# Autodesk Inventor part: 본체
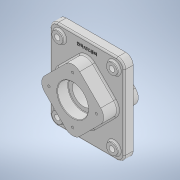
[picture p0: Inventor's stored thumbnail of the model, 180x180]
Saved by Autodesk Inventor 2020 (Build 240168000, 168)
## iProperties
Created: 2021-07
Part Number: 본체
Material: 일반
Document SubType Name: Modeling
Designer: Owner
Density: 1 g/cm^3
Appearance: 기본값
Author: Owner
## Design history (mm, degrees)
sketch "스케치1"
  geometry: L1 (75, 90)-(-75, 90); L2 (-75, 90)-(-75, -90); L3 (-75, -90)-(75, -90); L4 (75, -90)-(75, 90); L5 (75, 90)-(-75, -90); L6 (-75, 90)-(75, -90); 1 further point
  constraints: 12 end point, 2 midpoint, 2 parallel, 1 horizontal, 1 perpendicular
  dimensions: "d0" = 150 distance of L1.start L1.end; "d1" = 180 distance between parallel lines of L3 L1
extrude "돌출1" new body sketch "스케치1" stored distance "d2" = 18; taper "d3" = 0 deg
sketch "스케치2"
  geometry: L1 (-56.569, 14.142)-(-14.142, 56.569); L2 (14.142, 56.569)-(56.569, 14.142); L3 (56.569, -14.142)-(14.142, -56.569); L4 (-14.142, -56.569)-(-56.569, -14.142); L5 (-70.711, 0)-(70.711, 0); L6 (0, 70.711)-(0, -70.711); A1 r 20 centre (0, 42.426) between (14.142, 56.569) and (-14.142, 56.569); A2 r 20 centre (42.426, 0) between (56.569, -14.142) and (56.569, 14.142); A3 r 20 centre (0, -42.426) between (-14.142, -56.569) and (14.142, -56.569); A4 r 20 centre (-42.426, 0) between (-56.569, 14.142) and (-56.569, -14.142); 1 further point
  constraints: 12 end point, 8 point on circle, 8 point on line, 8 tangent, 4 centre point, 3 equal radius, 2 midpoint, 2 parallel, 1 perpendicular, 1 vertical
  dimensions: "d4" = 100 distance of L6.start L5.end; "d5" = 45 deg angle of L6 L2; "d6" = 20 radius of A1
extrude "돌출2" join sketch "스케치2" distance "d7" = 29; taper "d8" = 0 deg
extrude "돌출3" join sketch "스케치2" distance "d9" = 41; taper "d10" = 0 deg
sketch "스케치3"
  geometry: L1 (0, 38)-(0, -32); L2 (-14.142, -32)-(14.142, -32) reference; L3 (56.569, 38)-(14.142, 38) reference; L4 (31, 38)-(31, 16); L5 (31, 16)-(22.5, 16); L6 (22.5, 16)-(22.5, -10); L7 (31, -10)-(31, -32); L8 (14.142, -32)-(56.569, -32) reference; L9 (31, -10)-(22.5, -10); L10 (14.142, 38)-(-14.142, 38) reference; 1 further point
  constraints: 12 end point, 4 point on line, 2 vertical, 1 midpoint, 1 perpendicular
  dimensions: "d11" = 62 diameter of L4 L1; "d12" = 45 diameter of L6 L1; "d13" = 22 distance between parallel lines of L5 L3; "d14" = 22 distance between parallel lines of L8 L9
revolve "회전1" sketch "스케치3" stored, may be unused: angle "d15" = 90 deg
fillet "모깎기1" dims "d16" = 15
sketch "스케치4"
  geometry: 2 further points
  constraints: 1 vertical alignment
  dimensions: "d17" = 48 distance of point (0, 0) point (0, 48)
hole "구멍1" sketch "스케치4" at (0, 48) diameter "d18" = 4.917; stored, may be unused: countersink angle "d22" = 90 deg, drill point angle "d24" = 118 deg; dims "d19" = 10, "d20" = 4, "d21" = 2, "d23" = 13
sketch "스케치5"
  geometry: 2 further points
  constraints: 1 vertical alignment
  dimensions: "d28" = 48 distance of point (0, 0) point (0, 48)
hole "구멍2" sketch "스케치5" at (0, 48) diameter "d29" = 4.917; stored, may be unused: countersink angle "d33" = 90 deg, drill point angle "d35" = 118 deg; dims "d30" = 10, "d31" = 4, "d32" = 2, "d34" = 13
sketch "스케치6"
  geometry: L1 (60, 90)-(-60, 90) reference; L2 (75, -75)-(75, 75) reference; L3 (-75, 75)-(-75, -75) reference; C1 r 11 at (55, 70); C2 r 11 at (-55, 70); 1 further point
  constraints: 2 centre point
  dimensions: "d39" = 22 diameter of C1; "d40" = 20 distance from line of L1 C1.centre; "d41" = 20 distance from line of L2 C1.centre; "d42" = 22 diameter of C2; "d43" = 110 distance of C1.centre C2.centre; "d44" = 20 distance from line of L3 C2.centre
extrude "돌출4" join sketch "스케치6" distance "d45" = 5; taper "d46" = 0 deg
sketch "스케치7"
  geometry: C1 r 11 at (0, 0) reference; 2 further points
  constraints: 1 coincident
hole "구멍3" sketch "스케치7" at (0, 0) diameter "d47" = 11; stored, may be unused: countersink angle "d51" = 90 deg, drill point angle "d53" = 0 deg; dims "d48" = 10, "d49" = 4, "d50" = 2, "d52" = 13
fillet "모깎기2" dims "d54" = 3
fillet "모깎기3" dims "d55" = 3
fillet "모깎기4" dims "d56" = 3
fillet "모깎기5" dims "d57" = 1
chamfer "모따기1" distance "d58" = 1; stored, may be unused: second distance "d59" = 2, angle "d60" = 45 deg
chamfer "모따기2" distance "d61" = 1; stored, may be unused: second distance "d62" = 2, angle "d63" = 45 deg
sketch "스케치8"
  geometry: L1 (60, 90)-(-60, 90) reference; 2 further points
  constraints: 1 vertical alignment, 1 other
  dimensions: "d64" = 15 distance from line of L1 point (0, 75)
feature "엠보싱1" sketch "스케치8" dims "d0" = 150, "d1" = 180, "d65" = 0.5, "d66" = 0
node "솔리드1"
pattern_circular "원형 패턴1" dims angle "d26" = 360 deg
pattern_circular "원형 패턴2" dims angle "d37" = 360 deg
mirror "미러1"
mirror "미러2"
mirror "미러3"
feature "A9D066F2-1C7D-4E18-AEED-F7BC21143FA4" dims "d47" = 11, "d48" = 10, "d49" = 4, "d50" = 2, "d51" = 90 deg, "d52" = 13, "d53" = 0
